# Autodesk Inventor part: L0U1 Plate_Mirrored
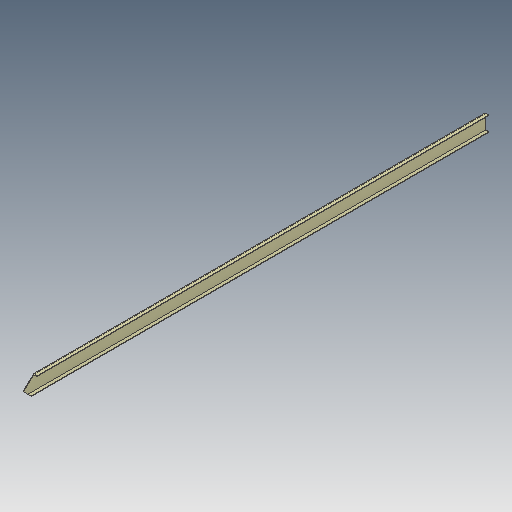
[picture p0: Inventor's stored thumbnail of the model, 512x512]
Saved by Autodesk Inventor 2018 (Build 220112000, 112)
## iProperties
Created: 2018-02
Part Number: L0U1 Plate_Mirrored
Material: Steel, Mild
Document SubType Name: Sheet Metal
Designer: STK
Density: 7.85 g/cm^3
Sheet Metal Rule: Default
Appearance: Semi-Polished
Author: STK
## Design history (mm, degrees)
derived "L0U1 Plate.ipt"
feature "Solid1::L0U1 Plate.ipt" dims "d0" = 10
tag "TaggingFeature1"
body "Solid1"
other parameters: "Thickness" = 3.048, "BendRadius" = 3.048 (= Thickness), "BendReliefWidth" = 3.048 (= Thickness), "BendReliefDepth" = 1.524 (= 0.5 x Thickness), "CornerReliefSize" = 12.192 (= 4 x Thickness), "SeamGap" = 0.00508, "MinimumRemnant" = 6.096 (= 2 x Thickness), "TransitionRadius" = 3.048 (= BendRadius), "JacobiRadiusSize" = 3.048 (= BendRadius), "GapSize" = 3.048 (= Thickness)
